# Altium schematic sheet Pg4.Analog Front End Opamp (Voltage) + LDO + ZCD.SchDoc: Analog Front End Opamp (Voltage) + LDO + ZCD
size 431 x 279 mm; Date: Not shown in title block; ApprovedBy: Not shown in title block; CheckedBy: Not shown in title block; Author: Not shown in title block; CompanyName: Not shown in title block; Engineer: Not shown in title block; Organization: Not shown in title block; Address1: Not shown in title block; Address2: Not shown in title block; Address3: Not shown in title block; Address4: Not shown in title block; DocumentNumber: 4; Revision: Use project parameter SCH_Rev; SheetNumber: 4; SheetTotal: 8; PageSetup: Record=PageOptions|CenterHorizontal=True|CenterVertical=True|PrintScale=1.00|XCorrection=1.00|YCorrection=1.00|PrintKind=0|BorderSize=5000000|LeftOffset=0|BottomOffset=0|Orientation=2|PaperLength=1000|PaperWidth=1000|Scale=100|PaperSource=15|PrintQuality=600|MediaType=1|DitherType=10|PaperKind=Letter|PrintScaleMode=1
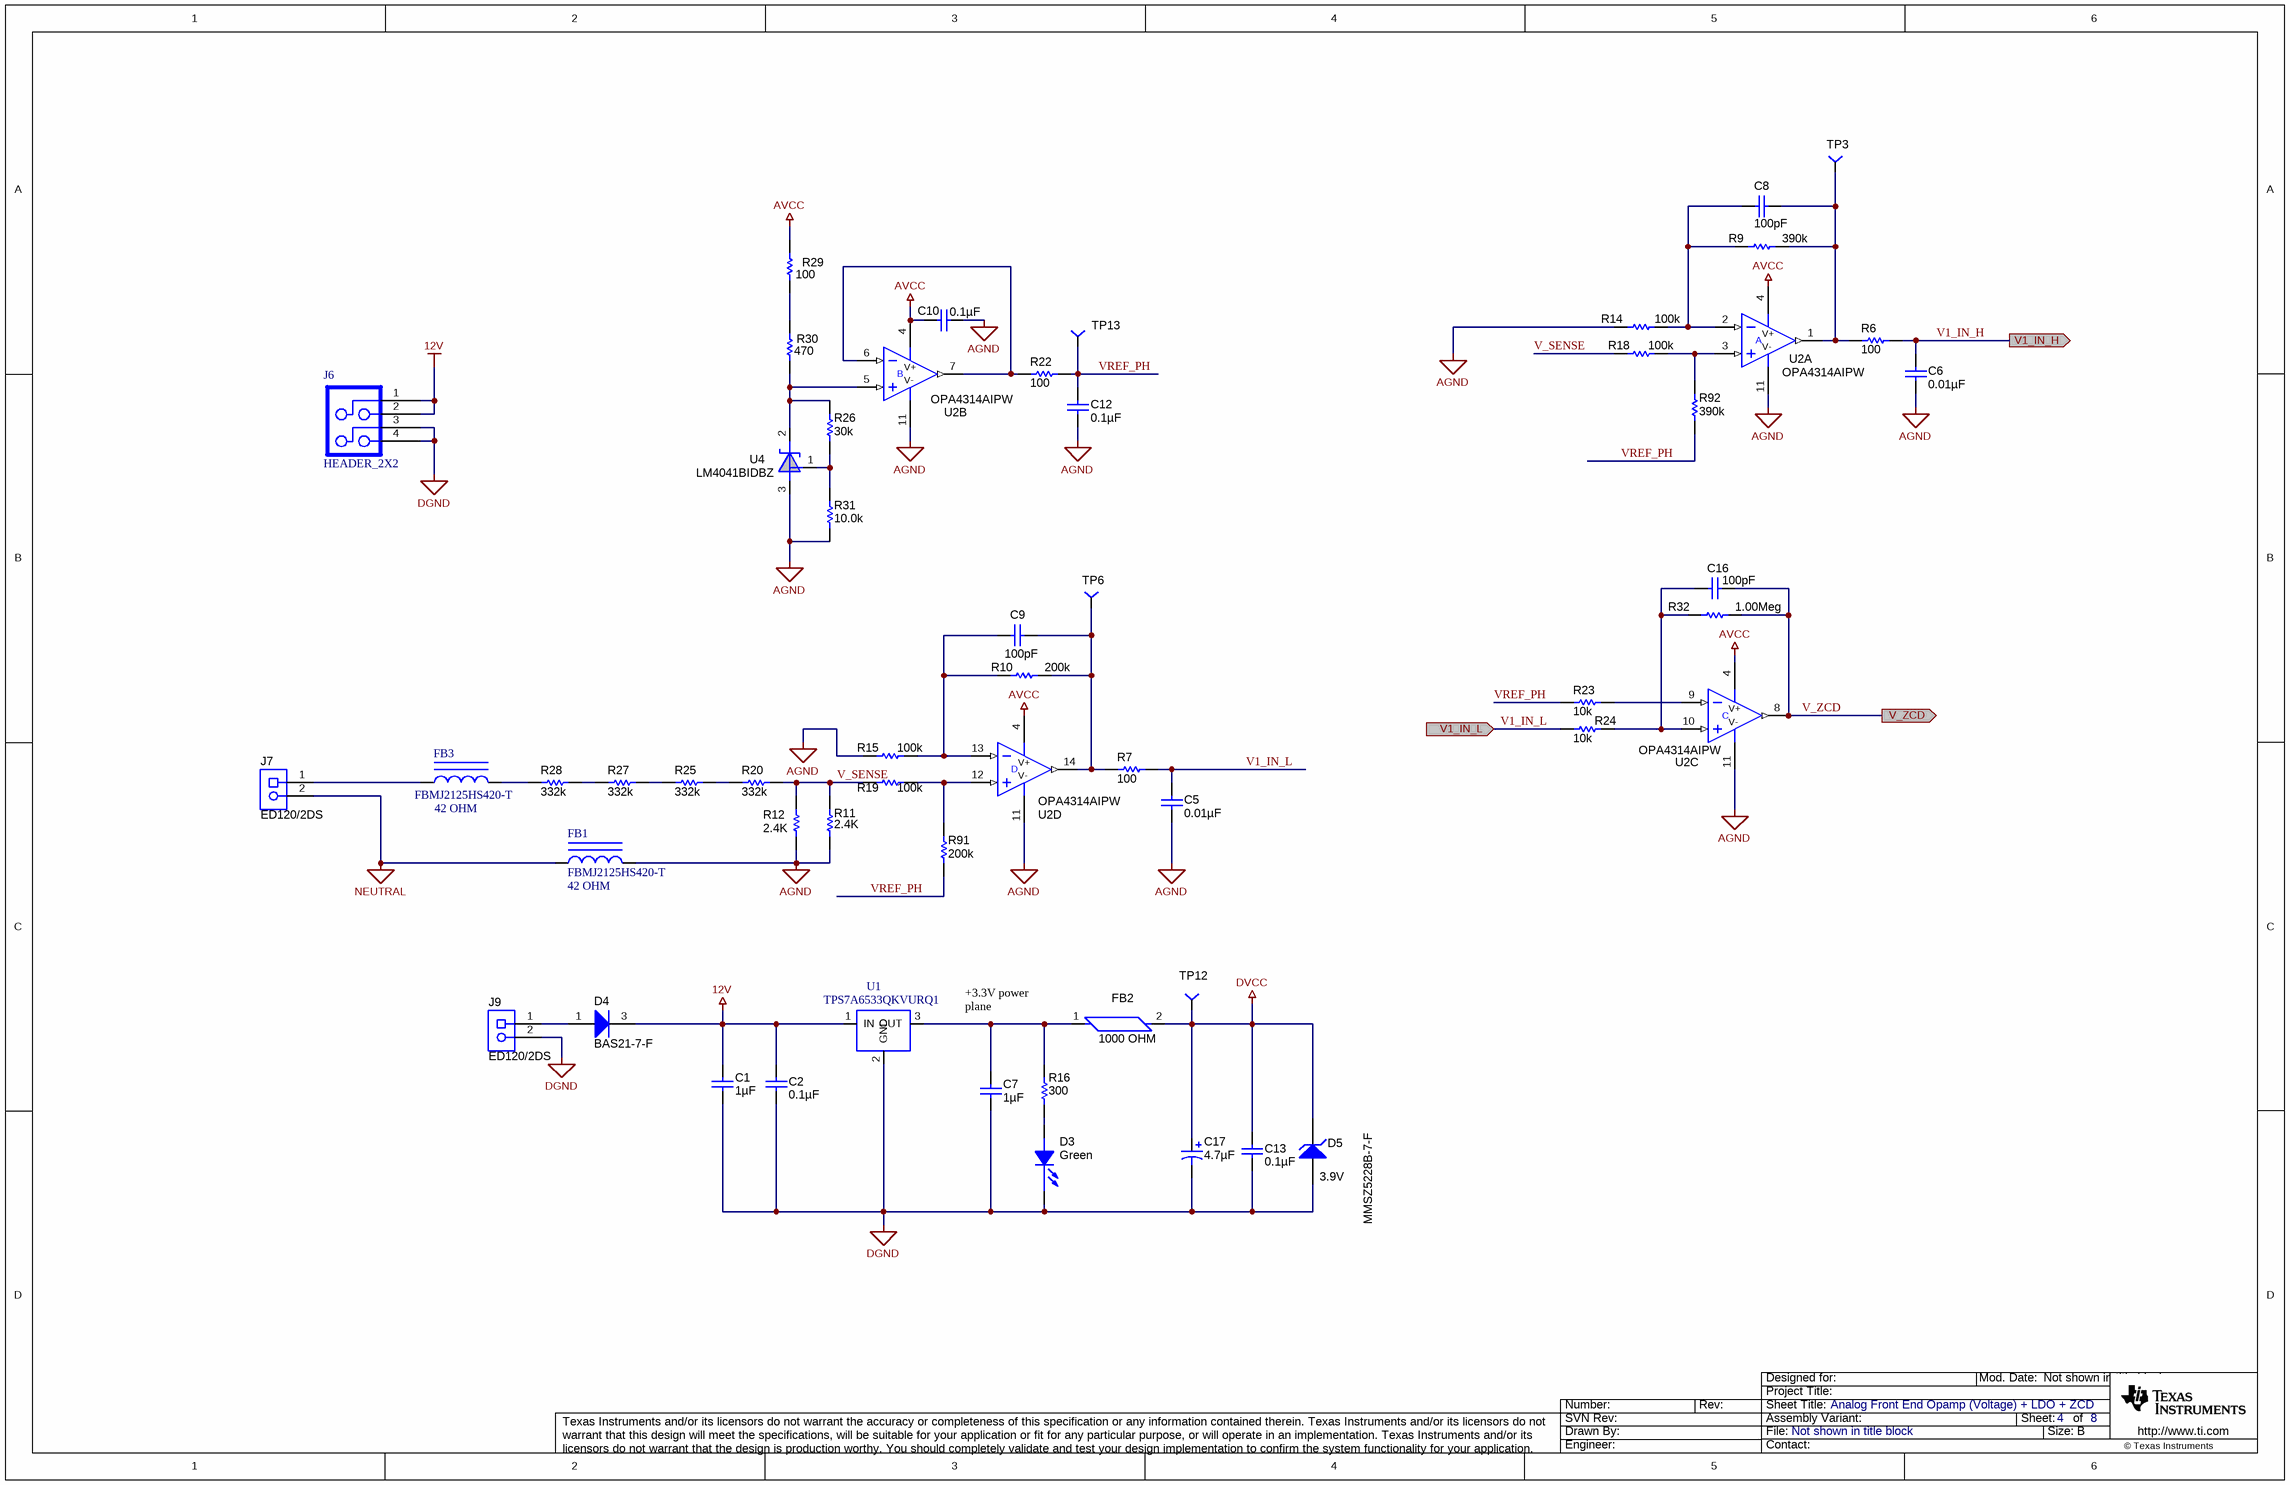
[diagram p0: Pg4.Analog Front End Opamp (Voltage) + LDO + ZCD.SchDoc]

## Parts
C1  ValueDisplayed: 1µF  [0603]  (hidden comment: C1608X7R1C105K)
C2  ValueDisplayed: 0.1µF  [0603]  (hidden comment: C0603C104K5RACTU)
C5  ValueDisplayed: 0.01µF  [0603]  (hidden comment: C1608C0G1E103J)
C6  ValueDisplayed: 0.01µF  [0603]  (hidden comment: C1608C0G1E103J)
C7  ValueDisplayed: 1µF  [0603]  (hidden comment: C1608X7R1C105K)
C8  ValueDisplayed: 100pF  [0603]  (hidden comment: 06035A101FAT2A)
C9  ValueDisplayed: 100pF  [0603]  (hidden comment: 06035A101FAT2A)
C10  ValueDisplayed: 0.1µF  [0603]  (hidden comment: 06033C104JAT2A)
C12  ValueDisplayed: 0.1µF  [0603]  (hidden comment: 06033C104JAT2A)
C13  ValueDisplayed: 0.1µF  [0603]  (hidden comment: C0603C104K5RACTU)
C16  ValueDisplayed: 100pF  [0603]  (hidden comment: 06035A101FAT2A)
C17  ValueDisplayed: 4.7µF  [6032-28]  (hidden comment: 293D475X9035C2TE3)
D3  value Green  [LED0603AA]  (hidden comment: LED_LG L29K-G2J1-24-Z)
D4  BAS21-7-F  [SOT-23]
D5  MMSZ5228B-7-F  value 3.9V  [sod-123]
FB1  FBMJ2125HS420-T  value 42 OHM  [0805_hv]
FB2  1000 OHM  [0603]
FB3  FBMJ2125HS420-T  value 42 OHM  [0805_hv]
J6  HEADER_2X2  [HDR_2X2]
J7  ED120/2DS  [CONN_ED120-2DS]
J9  ED120/2DS  [CONN_ED120-2DS]
R6  value 100  [0603]  (hidden comment: CRCW0603100RFKEA)
R7  value 100  [0603]  (hidden comment: CRCW0603100RFKEA)
R9  value 390k  [0603]  (hidden comment: CRCW0603390KFKEA)
R10  value 200k  [0603]  (hidden comment: CRCW0603200KFKEA)
R11  value 2.4K  [0805_hv]  (hidden comment: CRCW08052K40FKEA)
R12  value 2.4K  [0805_hv]  (hidden comment: CRCW08052K40FKEA)
R14  value 100k  [0603]  (hidden comment: CRCW0603100KFKEA)
R15  value 100k  [0603]  (hidden comment: CRCW0603100KFKEA)
R16  value 300  [0603]  (hidden comment: CRCW0603300RJNEA)
R18  value 100k  [0603]  (hidden comment: CRCW0603100KFKEA)
R19  value 100k  [0603]  (hidden comment: CRCW0603100KFKEA)
R20  value 332k  [0805_HV]  (hidden comment: CRCW0805332KFKEA)
R22  value 100  [0603]  (hidden comment: CRCW0603100RFKEA)
R23  value 10k  [0603]  (hidden comment: CRCW060310K0JNEA)
R24  value 10k  [0603]  (hidden comment: CRCW060310K0JNEA)
R25  value 332k  [0805_HV]  (hidden comment: CRCW0805332KFKEA)
R26  value 30k  [0603]  (hidden comment: CRCW060330K0JNEA)
R27  value 332k  [0805_HV]  (hidden comment: CRCW0805332KFKEA)
R28  value 332k  [0805_HV]  (hidden comment: CRCW0805332KFKEA)
R29  value 100  [0603]  (hidden comment: CRCW0603100RFKEA)
R30  value 470  [0603]  (hidden comment: CRCW0603470RJNEA)
R31  value 10.0k  [0603]  (hidden comment: CRCW060310K0FKEA)
R32  value 1.00Meg  [0603]  (hidden comment: CRCW06031M00FKEA)
R91  value 200k  [0603]  (hidden comment: CRCW0603200KFKEA)
R92  value 390k  [0603]  (hidden comment: CRCW0603390KFKEA)
TP3  TP-040_RND  [TP-040_RND]  (value not drawn)
TP6  TP-040_RND  [TP-040_RND]  (value not drawn)
TP12  TP-040_RND  [TP-040_RND]  (value not drawn)
TP13  TP-040_RND  [TP-040_RND]  (value not drawn)
U1  TPS7A6533QKVURQ1  [KVU_1]
U2  OPA4314AIPW  [PW0014A_N]  (parts A,B,C,D of 4)
U4  LM4041BIDBZ  [SOT-23]

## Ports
V1_IN_H, V1_IN_L, V_ZCD

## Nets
12V: C1.1 C2.1 D4.3(K) J6.1 J6.2 U1.1(IN)
AGND: C5.1 C6.1 C10.1 C12.1 FB1.2 R11.2 R12.2 R14.2 R15.2 R31.1 U2.11(V-) U4.3(A)
AVCC: C10.2 R29.1 U2.4(V+)
DGND: C1.2 C2.2 C7.2 C13.2 C17.2(-) D3.1(C) D5.2(A) J6.3 J6.4 J9.2 U1.2(GND)
DVCC: C13.1 C17.1(+) D5.1(K) FB2.2 TP12.1
NEUTRAL: FB1.1 J7.2
V1_IN_H: C6.2 R6.2 ; port V1_IN_H
V1_IN_L: C5.2 R7.2 R24.2 ; port V1_IN_L
V_SENSE: R11.1 R12.1 R18.2 R19.2 R20.1
V_ZCD: C16.1 R32.2 U2.8(OUT) ; port V_ZCD
VREF_PH: C12.2 R22.2 R23.2 R91.1 R92.2 TP13.1
NetC7_1: C7.1 FB2.1 R16.2 U1.3(OUT)
NetC8_1: C8.1 R6.1 R9.1 TP3.1 U2.1(OUT)
NetC8_2: C8.2 R9.2 R14.1 U2.2(IN-)
NetC9_1: C9.1 R7.1 R10.1 TP6.1 U2.14(OUT)
NetC9_2: C9.2 R10.2 R15.1 U2.13(IN-)
NetC16_2: C16.2 R24.1 R32.1 U2.10(IN+)
NetD3_2: D3.2(A) R16.1
NetD4_1: D4.1(A) J9.1
NetFB3_1: FB3.1 J7.1
NetFB3_2: FB3.2 R28.2
NetR18_1: R18.1 R92.1 U2.3(IN+)
NetR19_1: R19.1 R91.2 U2.12(IN+)
NetR20_2: R20.2 R25.1
NetR22_1: R22.1 U2.6(IN-) U2.7(OUT)
NetR23_1: R23.1 U2.9(IN-)
NetR25_2: R25.2 R27.1
NetR26_1: R26.1 R31.2 U4.1(FB)
NetR26_2: R26.2 R30.1 U2.5(IN+) U4.2(C)
NetR27_2: R27.2 R28.1
NetR29_2: R29.2 R30.2

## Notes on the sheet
- (near FB2) +3.3V power
  plane

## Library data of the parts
C1 C7 = C1608X7R1C105K: CAP, CERM, 1uF, 16V, +/-10%, X7R, 0603; Manufacturer: TDK; Polarized: N; CompType: Capacitor; U/M: EA; Cap_F: 0.000001; Tolerance_%: 10; ESR_Ohm: 0.0057; Value1: 0.0057 ohm; VDC_V: 16; TaMin_C: -55; TaMax_C: 125
C2 C13 = C0603C104K5RACTU: CAP, CERM, 0.1uF, 50V, +/-10%, X7R, 0603; Manufacturer: Kemet; Polarized: N; CompType: Capacitor; U/M: EA; Cap_F: 0.0000001; Tolerance_%: 10; Value1: Unknown; VDC_V: 50; TaMin_C: -55; TaMax_C: 125
C5 C6 = C1608C0G1E103J: CAP, CERM, 0.01uF, 25V, +/-5%, C0G/NP0, 0603; Manufacturer: TDK; Polarized: N; CompType: Capacitor; U/M: EA; Cap_F: 0.00000001; Tolerance_%: 5; Value1: Unknown; VDC_V: 25; TaMin_C: -55; TaMax_C: 125
C8 C9 C16 = 06035A101FAT2A: CAP, CERM, 100pF, 50V, +/-1%, C0G/NP0, 0603; Manufacturer: AVX; Polarized: N; CompType: Capacitor; U/M: EA; Cap_F: 0.0000000001; Tolerance_%: 1; Value1: Unknown; VDC_V: 50; TaMin_C: -55; TaMax_C: 125
C10 C12 = 06033C104JAT2A: CAP, CERM, 0.1uF, 25V, +/-5%, X7R, 0603; Manufacturer: AVX; Polarized: N; CompType: Capacitor; U/M: EA; Cap_F: 0.0000001; Tolerance_%: 5; ESR_Ohm: 0.05; Value1: 0.05 ohm; VDC_V: 25; TaMin_C: -55; TaMax_C: 125
C17 = 293D475X9035C2TE3: CAP, TA, 4.7uF, 35V, +/-10%, 1.9 ohm, SMD; Manufacturer: Vishay-Sprague; Polarized: Y; CompType: Capacitor; U/M: EA; Cap_F: 0.0000047; Tolerance_%: 10; Value1: 1.9 ohm; VDC_V: 35; ESR_Ohm: 1.9; IRMS_A: 0.24; TaMin_C: -55; TaMax_C: 125; Cap_Case: C
D3 = LED_LG L29K-G2J1-24-Z: LED SmartLED Green 570NM; Manufacturer: OSRAM; SymbolCreator: x0120606
D4 = BAS21-7-F: Diode, Switching, 200V, 0.2A, SOT-23; Manufacturer: Diodes Inc.; U/M: EA; Vf_V: 1.25; Value2: 1.25V; Io_A: 0.2; Vr_V: 200; TJmax_C: 150; RJC_CperW: 500
D5 = 1SMB5915BT3G: DIODE ZENER 3.9V 500MW SOD123; Manufacturer: Diodes Incorporated; U/M: EA; Power_W: 0.55; Vz_V: 3.9; Value1: 0.55W; RJA_CperW: 226
FB1 FB3 = FBMJ2125HS420-T: FERRITE BEAD, 42 OHM, 4 A, DCR0.008 OHM, SMT-0805; Manufacturer: TAIYO YUDEN; SymbolCreator: x0199378
FB2 = MMZ1608B102C: FERRITE CHIP 1000 OHM 300MA 0603; Manufacturer: TDK Corporation; CompType: Ferrite Bead
J6 = HEADER_2X2: Header, 2x2-pin, 100mil spacing; Manufacturer: FCI; PartNumber: 67997-404HLF; area: 40000; Value: PEC02DAAN
J7 J9 = ED120/2DS: TERMINAL BLOCK 5.08MM VERT 2POS, TH; Manufacturer: On-Shore Technology; SymbolCreator: a0412235; U/M: EA
R6 R7 R22 R29 = CRCW0603100RFKEA: RES, 100 ohm, 1%, 0.1W, 0603; Manufacturer: Vishay-Dale; CompType: Resistor; Value_Code: 100R; Tolerance_%: 1; Power_W: 0.1; VDC_V: 75; TempCo: 100 ppm/C; EIA_Code: E96; U/M: EA
R9 R92 = RC0603FR-0739KL: RES 390K OHM 1/10W 1% 0603 SMD; Manufacturer: Vishay Dale; CompType: Resistor; Tolerance_%: 1; Value2: 0.1W; TempCo: 100 ppm/C; U/M: EA
R10 R91 = CRCW0603200KFKEA: RES, 200k ohm, 1%, 0.1W, 0603; Manufacturer: Vishay-Dale; CompType: Resistor; Res_ohm: 200000; Tolerance_%: 1; Power_W: 0.1; VDC_V: 75; TempCo: 100 ppm/C; EIA_Code: E96; U/M: EA
R11 R12 = CRCW120610K0FKEA: RES 2.40K OHM 1/8W 1% 0805 SMD; Manufacturer: Vishay-Dale; CompType: Resistor; Tolerance_%: 1; Power_W: 0.125W; TempCo: 100 ppm/C; U/M: EA
R14 R15 R18 R19 = CRCW0603100KFKEA: RES, 100k ohm, 1%, 0.1W, 0603; Manufacturer: Vishay-Dale; CompType: Resistor; Res_ohm: 100000; Tolerance_%: 1; Power_W: 0.1; VDC_V: 75; TempCo: 100 ppm/C; EIA_Code: E96; U/M: EA
R16 = CRCW0603300RJNEA: RES, 300 ohm, 5%, 0.1W, 0603; Manufacturer: Vishay-Dale; CompType: Resistor; Value_Code: 300R; Tolerance_%: 5; Power_W: 0.1; VDC_V: 75; TempCo: 200 ppm/C; EIA_Code: E24; U/M: EA
R20 R25 R27 R28 = CRCW0805332KFKEA: RES, 332k ohm, 1%, 0.125W, 0805; Manufacturer: Vishay-Dale; CompType: Resistor; Res_ohm: 332000; Tolerance_%: 1; Power_W: 0.125; VDC_V: 150; TempCo: 100 ppm/C; EIA_Code: E96; U/M: EA
R23 R24 = RNCF0603TKY10K0: RES 10K OHM 1/10W 5% 0603 SMD; Manufacturer: Vishay-Dale; CompType: Resistor; Res_ohm: 10000; Value_Code: 10k0; Tolerance_%: 0.01; Value1: 0.01%; Power_W: 0.063; Value2: 0.063W; VDC_V: 50; TempCo: 5 ppm/C; U/M: EA
R26 = CRCW060330K0JNEA: RES, 30k ohm, 5%, 0.1W, 0603; Manufacturer: Vishay-Dale; CompType: Resistor; Res_ohm: 30000; Value_Code: 30k0; Tolerance_%: 5; Power_W: 0.1; VDC_V: 75; TempCo: 200 ppm/C; EIA_Code: E24; U/M: EA
R30 = CRCW0603470RJNEA: RES, 470 ohm, 5%, 0.1W, 0603; Manufacturer: Vishay-Dale; CompType: Resistor; Value_Code: 470R; Tolerance_%: 5; Power_W: 0.1; VDC_V: 75; TempCo: 200 ppm/C; EIA_Code: E24; U/M: EA
R31 = CRCW060310K0FKEA: RES, 10.0k ohm, 1%, 0.1W, 0603; Manufacturer: Vishay-Dale; CompType: Resistor; Res_ohm: 10000; Value_Code: 10k0; Tolerance_%: 1; Power_W: 0.1; VDC_V: 75; TempCo: 100 ppm/C; EIA_Code: E96; U/M: EA
R32 = CRCW06031M00FKEA: RES 1.00M OHM 1/10W 1% 0603 SMD; Manufacturer: Vishay-Dale; CompType: Resistor; Res_ohm: 1000000; Value_Code: 1M00; Tolerance_%: 1; Power_W: 0.1; Value2: 0.1W; VDC_V: 75; TempCo: 100 ppm/C; EIA_Code: E96; U/M: EA
TP3 TP6 TP12 TP13 = TP-040_RND: Test Point, O.040 Hole; Manufacturer: STD; Value: STD
U1 = TPS7A6533QKVURQ1: IC, 300-mA 40-V LOW-DROPOUT REGULATOR WITH 25-uA QUIESCENT CURRENT; Manufacturer: TI; Alternate Manufacturer: None; Area: 136210
U2 = LMV324IPW: LOW-VOLTAGE RAIL-TO-RAIL OUTPUT OPERATIONAL AMPLIFIERS, PW0014A; Alternate Manufacturer: None; Manufacturer: Texas Instruments; SymbolCreator: a0411947; CompType: IC; U/M: EA
U4 = LM4041BIDBZ: IC, Micropower Shunt Voltage Reference 100 ppm/°C, 45µA-12mA,  Adjustable; Manufacturer: TI; Alternate Manufacturer: None; Area: 25500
